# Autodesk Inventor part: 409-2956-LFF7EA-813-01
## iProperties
Created: 2010-11
Part Number: 409-2956-LFF7EA-813-01
Material: 3/8" OD TUBE - SS
Description: PT TUBING
Document SubType Name: Modeling
Designer: S. Boerckel
Engineer: Steve Boerckel
Mass: 769.029 g
Surface Area: 1665.99 cm^2
Volume: 95.1769 cm^3
Density: 8.08 g/cm^3
Length: 140.652 in
Author: S. Boerckel
Revision Number: 0
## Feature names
1. Sweep1
